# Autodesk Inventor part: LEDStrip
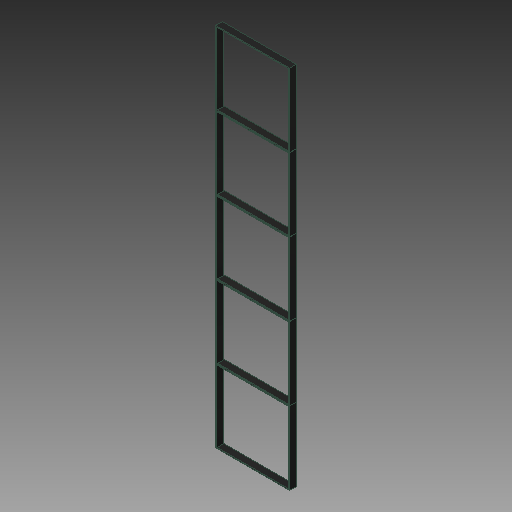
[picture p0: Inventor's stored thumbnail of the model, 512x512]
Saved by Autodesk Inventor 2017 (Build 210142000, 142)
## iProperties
Created: 2017-05
Part Number: LEDStrip
Material: Generic
Document SubType Name: Modeling
Designer: Savy
Density: 1 g/cm^3
Appearance: Default
Author: Savy
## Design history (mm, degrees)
feature "SOLID1"
body "Solid1"
